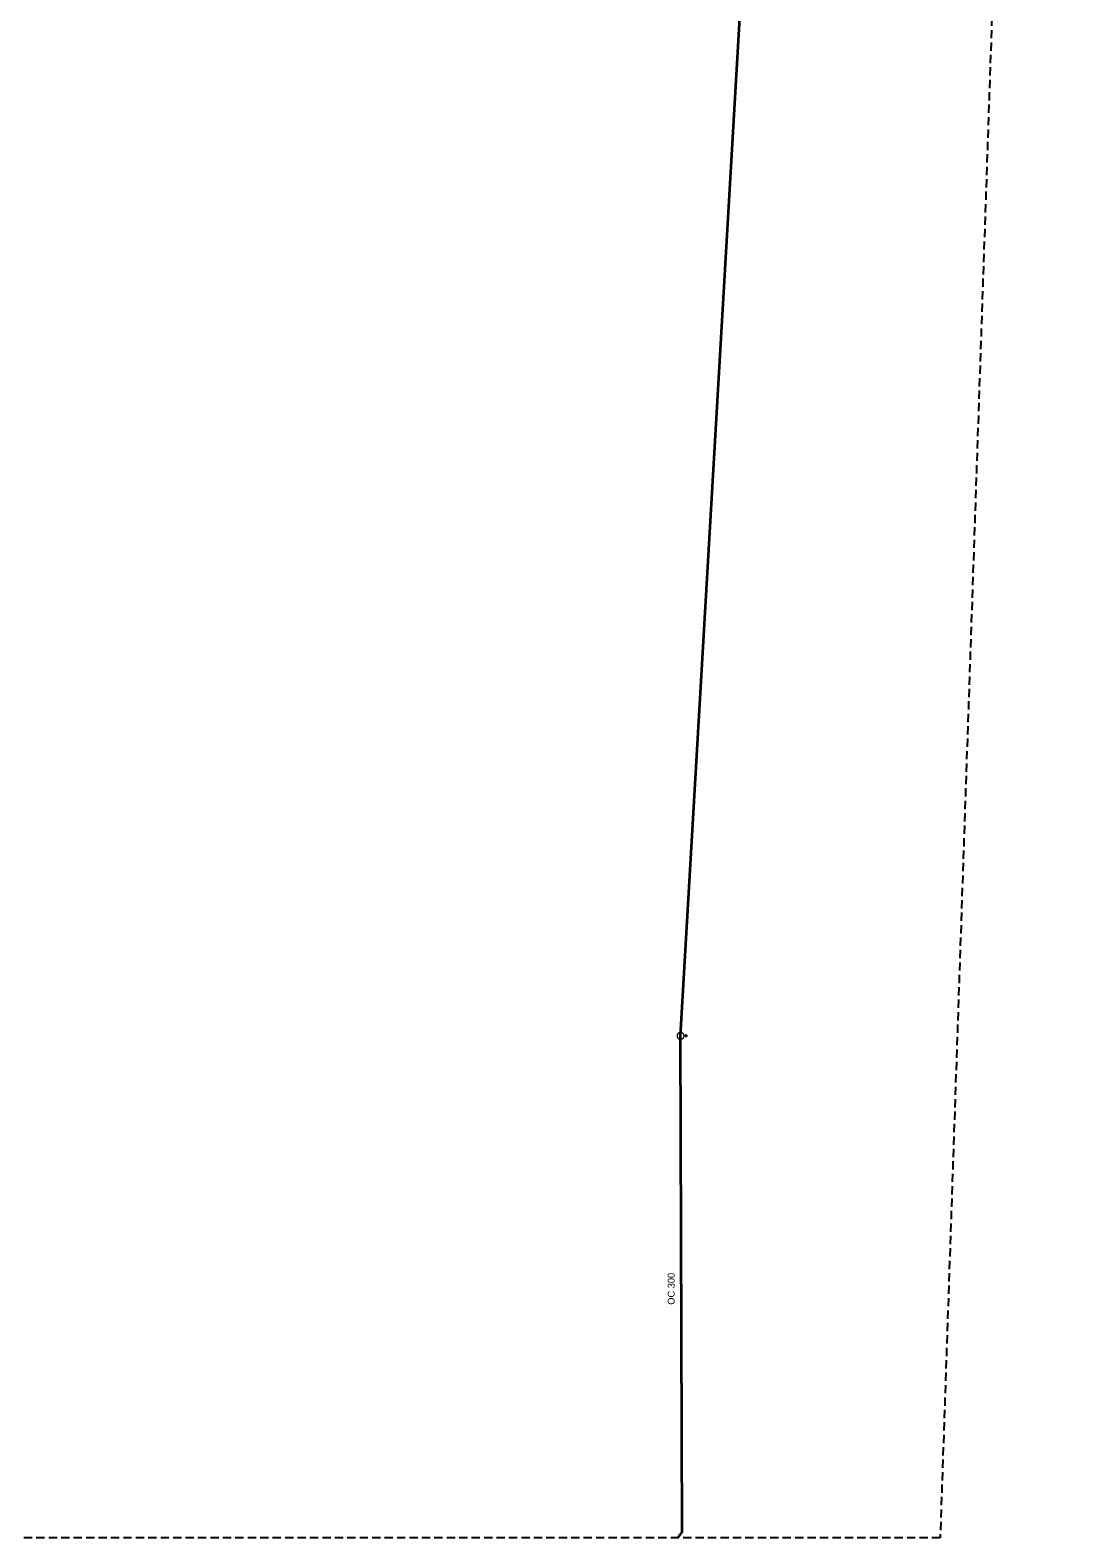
# Model space of a CAD drawing. Extents: x -724325 to -723665, y -972119 to -970722.
# Drawn here: x -723817.8 to -723665.1, y -972118.8 to -971900.7 of the extents above; entities that cross this region are included whole.
import ezdxf

# ---------------------------------------------------------------- set-up
doc = ezdxf.new("R2010")
doc.units = 0
doc.header["$LTSCALE"] = 0.4
doc.linetypes.add('MEDIUM_DASHED', pattern=[4.5, 3, -1.5])
for name, color, linetype, lineweight in [('1', 7, 'Continuous', 25), ('17', 7, 'Continuous', 35), ('23', 7, 'Continuous', 13)]:
    doc.layers.add(name, color=color, linetype=linetype, lineweight=lineweight)

msp = doc.modelspace()

# ---------------------------------------------------------------- linework, layer by layer
at = {"layer": '1', "linetype": 'MEDIUM_DASHED'}
msp.add_lwpolyline([(-724178.033, -970726.408), (-723849.368, -970722.221), (-723876.582, -971170.211), (-723665.148, -971503.063), (-723686.082, -972118.833), (-723917.752, -972118.833), (-723962.412, -971393.118), (-724325.27, -971133.535)], close=True, dxfattribs=at)
at = {"layer": '17'}
msp.add_line((-723723.649, -972046.19), (-723706.064, -971743.847), dxfattribs=at)
msp.add_lwpolyline([(-723724.064, -972118.833), (-723723.419, -972117.993), (-723723.649, -972046.19)], dxfattribs=at)
at = {"layer": '23'}
for p, q in [((-723722.692, -972046.18), (-723723.157, -972046.182)), ((-723722.94, -972046.017), (-723722.94, -972046.182)), ((-723722.938, -972046.347), (-723722.692, -972046.18)), ((-723722.917, -972046.031), (-723722.916, -972046.331)), ((-723722.889, -972046.048), (-723722.888, -972046.315)), ((-723722.866, -972046.066), (-723722.864, -972046.294)), ((-723722.843, -972046.083), (-723722.84, -972046.279)), ((-723722.818, -972046.098), (-723722.816, -972046.264)), ((-723722.791, -972046.114), (-723722.79, -972046.248)), ((-723722.767, -972046.13), (-723722.765, -972046.231)), ((-723722.743, -972046.149), (-723722.742, -972046.213)), ((-723722.716, -972046.164), (-723722.715, -972046.196))]:
    msp.add_line(p, q, dxfattribs=at)
msp.add_lwpolyline([(-723723.645, -972046.69), (-723723.593, -972046.686), (-723723.542, -972046.679), (-723723.491, -972046.665), (-723723.442, -972046.646), (-723723.395, -972046.622), (-723723.352, -972046.592), (-723723.312, -972046.559), (-723723.274, -972046.522), (-723723.242, -972046.482), (-723723.214, -972046.438), (-723723.19, -972046.391), (-723723.173, -972046.34), (-723723.158, -972046.291), (-723723.15, -972046.238), (-723723.149, -972046.186), (-723723.153, -972046.135), (-723723.16, -972046.083), (-723723.174, -972046.032), (-723723.192, -972045.985), (-723723.216, -972045.938), (-723723.246, -972045.894), (-723723.279, -972045.853), (-723723.317, -972045.815), (-723723.357, -972045.784), (-723723.401, -972045.755), (-723723.448, -972045.731), (-723723.497, -972045.714), (-723723.547, -972045.701), (-723723.599, -972045.693), (-723723.652, -972045.69), (-723723.703, -972045.694), (-723723.755, -972045.701), (-723723.806, -972045.715), (-723723.854, -972045.734), (-723723.901, -972045.759), (-723723.945, -972045.787), (-723723.986, -972045.82), (-723724.022, -972045.857), (-723724.054, -972045.898), (-723724.083, -972045.942), (-723724.107, -972045.989), (-723724.125, -972046.038), (-723724.138, -972046.09), (-723724.146, -972046.142), (-723724.148, -972046.194), (-723724.144, -972046.246), (-723724.136, -972046.297), (-723724.123, -972046.348), (-723724.105, -972046.396), (-723724.08, -972046.443), (-723724.052, -972046.486), (-723724.018, -972046.525), (-723723.981, -972046.562), (-723723.94, -972046.597), (-723723.896, -972046.625), (-723723.849, -972046.649), (-723723.8, -972046.666), (-723723.749, -972046.679), (-723723.697, -972046.688)], close=True, dxfattribs=at)
msp.add_lwpolyline([(-723722.692, -972046.18), (-723722.94, -972046.017), (-723722.938, -972046.347)], dxfattribs=at)

# ---------------------------------------------------------------- texts
at = {"layer": '1'}
msp.add_text('OC 300', height=1, rotation=90, dxfattribs=at).set_placement((-723724.509, -972085.094))

doc.saveas('drawing.dxf')
